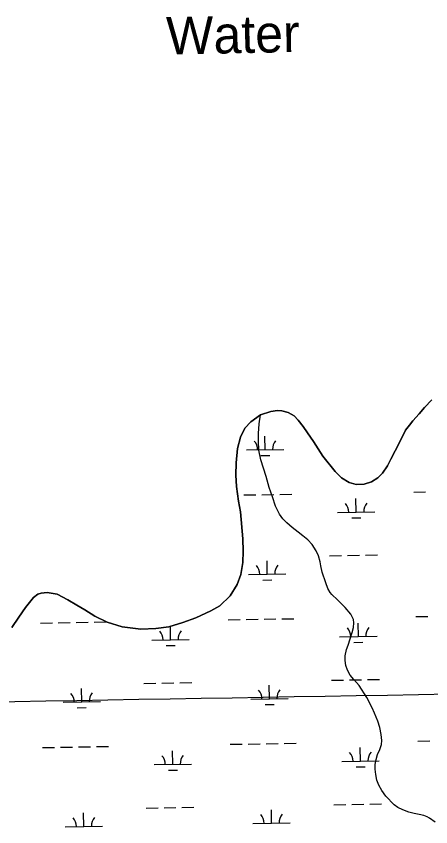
# Model space of a CAD drawing. Extents: x 3892998 to 3931244, y 278583 to 304547.
# Drawn here: x 3911257 to 3912365, y 296042 to 298208 of the extents above; entities that cross this region are included whole.
import ezdxf

# ---------------------------------------------------------------- set-up
doc = ezdxf.new("R2010")
doc.units = 0
for name, color, linetype in [('V-GRID-MAJR', 7, 'Continuous'), ('V-RIVR-IDEN', 7, 'Continuous'), ('V-TOPO-SHOR', 7, 'Continuous'), ('V-WETL-SWMP', 7, 'Continuous')]:
    doc.layers.add(name, color=color, linetype=linetype)

msp = doc.modelspace()

# ---------------------------------------------------------------- linework, layer by layer
at = {"layer": 'V-GRID-MAJR'}
msp.add_spline([(3897060.6180000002, 296135.19), (3902372.4110000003, 296225.205), (3907684.191, 296315.993), (3912995.9590000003, 296407.553), (3918307.7120000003, 296499.886), (3923619.453, 296592.991), (3928931.179, 296686.869), (3928931.18, 296686.869)], degree=3, dxfattribs=at)
at = {"layer": 'V-TOPO-SHOR'}
for points in [[(3912367.9110000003, 297183.397), (3912348.112, 297162.165), (3912333.903, 297145.84), (3912317.096, 297126.765), (3912308.08, 297115.35000000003), (3912297.4590000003, 297101.571), (3912281.444, 297068.866), (3912258.279, 297024.681), (3912249.204, 297006.529), (3912236.157, 296986.825), (3912223.565, 296974.253), (3912206.235, 296963.702), (3912186.767, 296957.922), (3912165.556, 296956.916), (3912146.5810000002, 296962.43), (3912126.6750000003, 296974.886), (3912109.781, 296991.874), (3912076.443, 297032.582), (3912051.216, 297071.24), (3912035.958, 297094.356), (3912024.217, 297111.696), (3912010.694, 297129.051), (3911999.494, 297140.045), (3911984.115, 297149.09500000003), (3911966.521, 297153.801), (3911955.038, 297154.893), (3911937.179, 297152.072), (3911909.693, 297142.981), (3911884.173, 297124.574), (3911867.773, 297106.881), (3911856.472, 297083.002), (3911848.681, 297052.753), (3911844.989, 297014.936), (3911844.11, 296981.855), (3911845.828, 296951.127), (3911851.436, 296911.844), (3911856.345, 296883.467), (3911862.265, 296811.68700000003), (3911863.369, 296778.587), (3911862.716, 296748.473), (3911857.287, 296716.221), (3911847.944, 296689.749), (3911828.861, 296659.596), (3911800.8910000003, 296632.888), (3911776.794, 296619.025), (3911737.0100000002, 296600.741), (3911702.028, 296588.36), (3911664.875, 296576.789), (3911629.965, 296572.531), (3911590.119, 296570.498), (3911540.4390000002, 296576.867), (3911499.919, 296588.70900000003), (3911467.362, 296604.64), (3911440.162, 296621.718), (3911418.671, 296633.99), (3911394.816, 296648.262), (3911366.017, 296663.371), (3911339.503, 296667.958), (3911323.639, 296666.50800000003), (3911314.3030000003, 296663.815), (3911302.9280000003, 296654.601), (3911281.895, 296627.832), (3911264.0360000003, 296602.027), (3911244.9760000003, 296574.45)], [(3912377.02, 296054.496), (3912361.881, 296065.109), (3912355.387, 296068.92), (3912346.122, 296072.561), (3912333.684, 296075.238), (3912321.048, 296077.919), (3912306.049, 296081.607), (3912290.472, 296087.28), (3912277.276, 296093.92), (3912267.647, 296100.924), (3912245.102, 296124.458), (3912234.154, 296139.386), (3912225.968, 296153.498), (3912220.9420000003, 296166.993), (3912218.1010000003, 296181.652), (3912216.647, 296196.697), (3912216.754, 296208.958), (3912219.039, 296221.795), (3912223.111, 296235.408), (3912229.353, 296248.409), (3912233.431, 296262.417), (3912234.315, 296273.288), (3912232.667, 296288.73), (3912228.481, 296307.95), (3912223.484, 296324.805), (3912214.5640000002, 296345.65), (3912208.16, 296360.14400000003), (3912194.3570000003, 296387.951), (3912173.664, 296419.579), (3912159.164, 296435.723), (3912149.577, 296447.87200000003), (3912142.1720000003, 296460.594), (3912137.924, 296472.892), (3912136.069, 296486.952), (3912136.566, 296499.012), (3912139.8740000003, 296515.597), (3912144.328, 296527.625), (3912149.815, 296544.587), (3912155.299, 296561.351), (3912158.58, 296574.971), (3912159.676, 296587.422), (3912158.365, 296596.137), (3912151.568, 296610.436), (3912136.6890000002, 296628.563), (3912126.687, 296638.34), (3912115.4990000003, 296648.326), (3912100.395, 296662.893), (3912096.282, 296667.87200000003), (3912089.657, 296679.204), (3912084.248, 296694.48), (3912074.6, 296722.65), (3912070.791, 296739.495), (3912069.103, 296750.388), (3912064.8880000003, 296766.246), (3912059.066, 296779.152), (3912047.937, 296796.257), (3912036.376, 296808.817), (3912023.414, 296819.608), (3912011.038, 296829.408), (3911994.7320000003, 296842.206), (3911980.005, 296854.594), (3911970.007, 296864.965), (3911960.4220000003, 296877.509), (3911950.123, 296898.759), (3911941.632, 296923.55700000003), (3911933.538, 296948.35000000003), (3911925.09, 296978.091), (3911918.356, 297000.103), (3911911.032, 297022.516), (3911905.912, 297048.075), (3911904.149, 297073.208), (3911904.3170000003, 297092.789), (3911905.931, 297119.278), (3911909.693, 297142.981)]]:
    msp.add_lwpolyline(points, dxfattribs=at)
at = {"layer": 'V-WETL-SWMP'}
for p, q in [((3911922.322694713, 297049.8116819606), (3911921.699622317, 297085.80628961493)), ((3911872.330184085, 297048.9463036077), (3911972.3152053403, 297050.67706031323)), ((3911910.591565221, 297034.17530252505), (3911934.587970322, 297034.59068413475)), ((3911849.0640530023, 296928.4545753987), (3911849.568042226, 296928.46329953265)), ((3911865.5656456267, 296928.7402206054), (3911897.5608524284, 296929.2940627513)), ((3911913.558455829, 296929.57098382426), (3911945.553662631, 296930.12482597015)), ((3911961.551266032, 296930.4017470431), (3911993.5464728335, 296930.95558918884)), ((3912165.715032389, 296883.18625285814), (3912165.0919599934, 296919.1808605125)), ((3912319.405655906, 296936.5962637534), (3912351.400862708, 296937.1501058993)), ((3912115.722521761, 296882.3208745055), (3912215.7075430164, 296884.05163121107)), ((3912153.9839028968, 296867.54987342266), (3912177.9803079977, 296867.9652550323)), ((3912094.315875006, 296766.501029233), (3912126.311081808, 296767.05487137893)), ((3912142.308685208, 296767.33179245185), (3912174.3038920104, 296767.88563459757)), ((3912190.301495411, 296768.1625556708), (3912222.296702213, 296768.71639781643)), ((3911928.0804894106, 296717.18651247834), (3911927.457417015, 296753.1811201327)), ((3911878.0879787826, 296716.32113412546), (3911978.0730000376, 296718.051890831)), ((3911916.349359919, 296701.5501330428), (3911940.3457650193, 296701.9655146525)), ((3911823.3306301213, 296595.2842879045), (3911855.325836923, 296595.83813005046)), ((3911871.323440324, 296596.11505112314), (3911903.3186471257, 296596.6688932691)), ((3911919.3162505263, 296596.945814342), (3911951.3114573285, 296597.49965648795)), ((3911967.309060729, 296597.77657756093), (3911999.304267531, 296598.3304197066)), ((3912325.1634506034, 296603.97109427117), (3912357.1586574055, 296604.5249364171)), ((3911321.497809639, 296586.5974815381), (3911353.4930164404, 296587.15132368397)), ((3911369.4906198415, 296587.4282447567), (3911401.485826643, 296587.9820869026)), ((3911417.4834300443, 296588.2590079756), (3911449.4786368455, 296588.8128501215)), ((3911465.476240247, 296589.08977119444), (3911497.4714470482, 296589.64361334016)), ((3911669.640006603, 296541.8742770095), (3911669.016934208, 296577.86888466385)), ((3912171.472827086, 296550.56108337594), (3912170.8497546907, 296586.5556910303)), ((3912121.4803164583, 296549.6957050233), (3912221.465337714, 296551.4264617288)), ((3911619.6474959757, 296541.0088986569), (3911719.6325172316, 296542.7396553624)), ((3912159.7416975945, 296534.9247039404), (3912183.7381026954, 296535.3400855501)), ((3911657.9088771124, 296526.23789757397), (3911681.9052822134, 296526.6532791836)), ((3911598.24084922, 296425.1890533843), (3911630.236056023, 296425.74289553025)), ((3911646.233659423, 296426.01981660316), (3911678.228866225, 296426.5736587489)), ((3911694.2264696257, 296426.8505798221), (3911726.221676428, 296427.40442196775)), ((3911933.8382841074, 296384.56134299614), (3911933.215211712, 296420.5559506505)), ((3912100.073669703, 296433.8758597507), (3912132.068876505, 296434.4297018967)), ((3912148.0664799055, 296434.70662296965), (3912180.0616867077, 296435.2604651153)), ((3912196.0592901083, 296435.5373861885), (3912228.05449691, 296436.0912283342)), ((3911432.005463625, 296375.8745366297), (3911431.3823912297, 296411.869144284)), ((3911382.0129529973, 296375.0091582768), (3911481.997974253, 296376.73991498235)), ((3911883.84577348, 296383.69596464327), (3911983.830794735, 296385.4267213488)), ((3911420.274334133, 296360.23815719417), (3911444.2707392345, 296360.6535388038)), ((3911922.107154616, 296368.9249635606), (3911946.103559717, 296369.3403451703)), ((3912330.921245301, 296271.34592478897), (3912362.916452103, 296271.89976693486)), ((3911327.2556043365, 296253.9723120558), (3911359.250811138, 296254.52615420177)), ((3911375.248414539, 296254.80307527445), (3911407.243621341, 296255.3569174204)), ((3911423.2412247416, 296255.6338384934), (3911455.2364315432, 296256.18768063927)), ((3911471.2340349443, 296256.46460171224), (3911503.229241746, 296257.0184438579)), ((3911829.088424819, 296262.65911842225), (3911861.0836316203, 296263.2129605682)), ((3911877.081235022, 296263.48988164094), (3911909.076441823, 296264.04372378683)), ((3911925.074045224, 296264.3206448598), (3911957.069252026, 296264.8744870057)), ((3911973.066855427, 296265.1514080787), (3912005.062062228, 296265.70525022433)), ((3912177.2306217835, 296217.9359138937), (3912176.607549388, 296253.930521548)), ((3911675.397801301, 296209.24910752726), (3911674.774728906, 296245.2437151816)), ((3911625.4052906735, 296208.3837291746), (3911725.390311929, 296210.1144858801)), ((3912127.2381111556, 296217.07053554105), (3912227.223132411, 296218.8012922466)), ((3912165.499492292, 296202.29953445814), (3912189.4958973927, 296202.71491606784)), ((3911663.6666718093, 296193.6127280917), (3911687.66307691, 296194.0281097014)), ((3911651.9914541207, 296093.39464712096), (3911683.986660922, 296093.9484892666)), ((3911699.9842643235, 296094.22541033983), (3911731.9794711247, 296094.77925248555)), ((3912105.8314644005, 296101.2506902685), (3912137.8266712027, 296101.8045324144)), ((3912153.824274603, 296102.0814534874), (3912185.819481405, 296102.6352956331)), ((3912201.8170848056, 296102.91221670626), (3912233.8122916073, 296103.466058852)), ((3911437.763258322, 296043.24936714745), (3911437.140185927, 296079.2439748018)), ((3911603.998643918, 296092.5638839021), (3911635.99385072, 296093.117726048)), ((3911939.596078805, 296051.9361735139), (3911938.9730064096, 296087.9307811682)), ((3911889.603568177, 296051.070795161), (3911989.588589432, 296052.8015518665)), ((3911387.770747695, 296042.3839887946), (3911487.7557689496, 296044.1147455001))]:
    msp.add_line(p, q, dxfattribs=at)
msp.add_lwpolyline([(3911244.9760000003, 296574.45), (3911264.037, 296602.027), (3911281.894, 296627.832), (3911302.929, 296654.60000000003), (3911314.3030000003, 296663.815), (3911323.639, 296666.509), (3911339.503, 296667.958), (3911366.0160000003, 296663.371), (3911394.816, 296648.263), (3911418.67, 296633.989), (3911440.163, 296621.718), (3911467.361, 296604.641), (3911499.919, 296588.708), (3911540.438, 296576.868), (3911590.1180000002, 296570.49700000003), (3911629.964, 296572.532), (3911664.875, 296576.79), (3911702.028, 296588.36), (3911737.009, 296600.741), (3911776.795, 296619.026), (3911800.89, 296632.888), (3911828.861, 296659.596), (3911847.944, 296689.749), (3911857.2860000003, 296716.221), (3911862.715, 296748.473), (3911863.369, 296778.586), (3911862.2660000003, 296811.686), (3911856.344, 296883.467), (3911851.435, 296911.844), (3911845.828, 296951.126), (3911844.11, 296981.854), (3911844.989, 297014.93700000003), (3911848.682, 297052.752), (3911856.471, 297083.002), (3911867.773, 297106.881), (3911884.173, 297124.574), (3911909.694, 297142.981), (3911937.18, 297152.07300000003), (3911955.038, 297154.892), (3911966.521, 297153.802), (3911984.116, 297149.094), (3911999.494, 297140.045), (3912010.694, 297129.051), (3912024.217, 297111.696), (3912035.958, 297094.356), (3912051.215, 297071.24), (3912076.444, 297032.582), (3912109.7800000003, 296991.873), (3912126.6750000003, 296974.886), (3912146.5810000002, 296962.43), (3912165.556, 296956.917), (3912186.767, 296957.923), (3912206.235, 296963.701), (3912223.565, 296974.252), (3912236.156, 296986.826), (3912249.205, 297006.529), (3912258.278, 297024.68), (3912281.444, 297068.867), (3912297.46, 297101.57), (3912308.08, 297115.349), (3912317.095, 297126.765), (3912333.903, 297145.841), (3912348.112, 297162.165), (3912367.9110000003, 297183.396)], dxfattribs=at)
for centre, radius, start, end in [((3911867.0798156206, 297049.3302932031), 35.24628790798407, 0.21988000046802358, 41.76353833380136), ((3911977.5491384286, 297051.24253484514), 35.24628790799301, 140.21987699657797, 181.7635353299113), ((3912110.4721532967, 296882.7048641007), 35.24628790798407, 0.21988000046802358, 41.76353833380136), ((3912220.941476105, 296884.6171057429), 35.24628790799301, 140.21987699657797, 181.7635353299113), ((3911872.837610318, 296716.70512372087), 35.24628790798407, 0.21988000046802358, 41.76353833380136), ((3911983.3069331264, 296718.6173653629), 35.24628790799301, 140.21987699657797, 181.7635353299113), ((3912116.2299479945, 296550.0796946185), 35.24628790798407, 0.21988000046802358, 41.76353833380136), ((3912226.6992708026, 296551.9919362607), 35.24628790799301, 140.21987699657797, 181.7635353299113), ((3911614.397127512, 296541.39288825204), 35.24628790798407, 0.21988000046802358, 41.76353833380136), ((3911724.86645032, 296543.3051298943), 35.24628790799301, 140.21987699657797, 181.7635353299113), ((3911376.7625845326, 296375.39314787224), 35.24628790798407, 0.21988000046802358, 41.76353833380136), ((3911487.231907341, 296377.3053895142), 35.24628790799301, 140.21987699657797, 181.7635353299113), ((3911878.595405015, 296384.07995423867), 35.24628790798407, 0.21988000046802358, 41.76353833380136), ((3911989.0647278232, 296385.9921958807), 35.24628790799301, 140.21987699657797, 181.7635353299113), ((3911620.1549222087, 296208.7677187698), 35.24628790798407, 0.21988000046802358, 41.76353833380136), ((3911730.6242450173, 296210.67996041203), 35.24628790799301, 140.21987699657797, 181.7635353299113), ((3912121.9877426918, 296217.4545251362), 35.24628790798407, 0.21988000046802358, 41.76353833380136), ((3912232.4570654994, 296219.36676677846), 35.24628790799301, 140.21987699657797, 181.7635353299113), ((3911884.3531997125, 296051.4547847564), 35.24628790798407, 0.21988000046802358, 41.76353833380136), ((3911994.822522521, 296053.3670263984), 35.24628790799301, 140.21987699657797, 181.7635353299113), ((3911382.5203792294, 296042.76797839), 35.24628790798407, 0.21988000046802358, 41.76353833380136), ((3911492.9897020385, 296044.680220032), 35.24628790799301, 140.21987699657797, 181.7635353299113)]:
    msp.add_arc(centre, radius, start, end, dxfattribs=at)

# ---------------------------------------------------------------- texts
at = {"layer": 'V-RIVR-IDEN'}
msp.add_text('Water', height=99.99980199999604, rotation=1.1584721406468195, dxfattribs=at).set_placement((3911658.949877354, 298105.24004413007))

doc.saveas('drawing.dxf')
